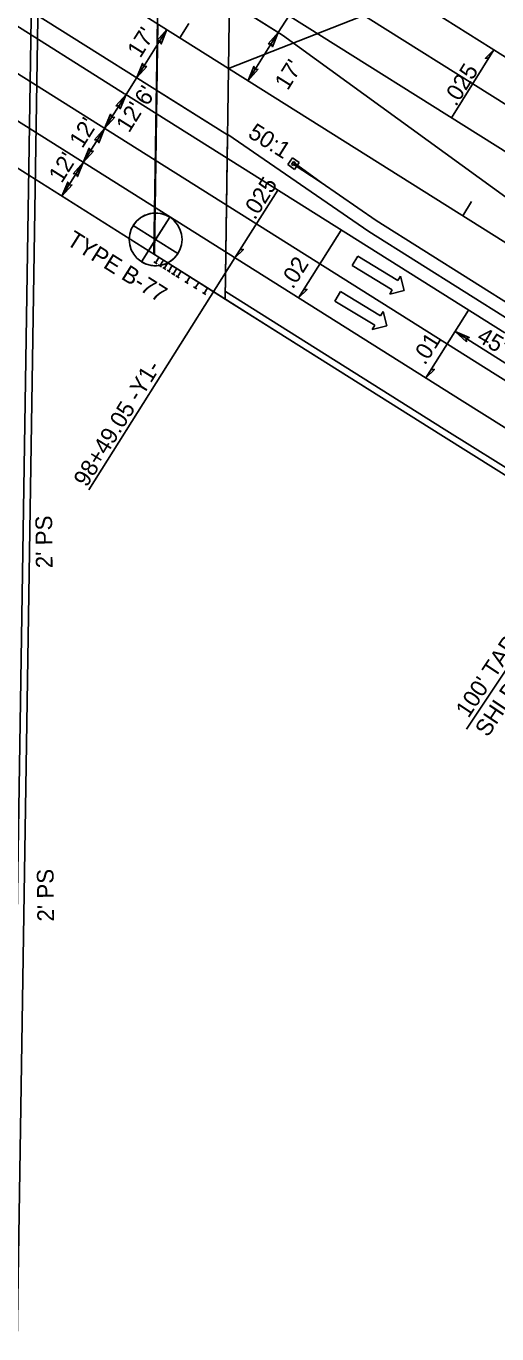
# Model space of a CAD drawing. Extents: x 2389694 to 2405615, y 547005 to 573532.
# Drawn here: x 2397764.3 to 2397905.2, y 552684.1 to 553075.7 of the extents above; entities that cross this region are included whole.
import ezdxf

# ---------------------------------------------------------------- set-up
doc = ezdxf.new("R2010")
doc.units = 0
for name, color, linetype in [('Boring Cell', 7, 'Continuous'), ('Default', 7, 'Continuous'), ('Old_Level_22', 7, 'Continuous'), ('Prop Approach Slab', 7, 'Continuous'), ('Prop Approach Slab Hatching', 7, 'Continuous'), ('Prop Cable Guiderail Anchor Unit CELL', 7, 'Continuous'), ('Prop Cable Guiderail Double Face', 7, 'Continuous'), ('Prop Conc Expressway Gutter', 7, 'Continuous'), ('Prop Dimension', 7, 'Continuous'), ('Prop Dimension Text', 7, 'Continuous'), ('Prop EOT', 7, 'Continuous'), ('Prop Guardrail', 7, 'Continuous'), ('Prop Horizontal Alignment', 7, 'Continuous'), ('Prop Horizontal Alignment Tick Small', 7, 'Continuous'), ('Prop Lane Arrow Through CELL', 7, 'Continuous'), ('Prop Lane Lines', 7, 'Continuous'), ('Prop SAU III Approach CELL', 7, 'Continuous'), ('Prop Super Arrow 1 Lane CELL', 7, 'Continuous'), ('Prop Superelevation Label', 7, 'Continuous')]:
    doc.layers.add(name, color=color, linetype=linetype)

# ---------------------------------------------------------------- blocks, each defined once
blk = doc.blocks.new('B02')
at = {"layer": 'Boring Cell'}
for p, q in [((0, -15.81), (0, 15.81)), ((0.1785, 15.81), (0, 15.81)), ((15.81, 0), (-15.81, 0)), ((15.81, 0), (15.81, 0.1785))]:
    blk.add_line(p, q, dxfattribs=at)
for points in [[(0, 15.81), (0, 0), (-15.81, 0)], [(0, -15.81), (0, 0), (15.81, 0)]]:
    blk.add_lwpolyline(points, dxfattribs=at)
blk.add_circle((0, 0), 15.81, dxfattribs=at)
for start, end in [(89.3557361, 180), (270, 0.6442639)]:
    blk.add_arc((0, 0), 15.81, start, end, dxfattribs=at)

msp = doc.modelspace()

# ---------------------------------------------------------------- linework, layer by layer
at = {"layer": 'Default'}
msp.add_line((2397804.86, 553153.2), (2397802.52, 553007.47), dxfattribs=at)
at = {"layer": 'Prop Approach Slab'}
for p, q in [((2397670.86, 553139.97), (2397824.62, 553043.14)), ((2397670.16, 553090.81), (2397823.92, 552993.99)), ((2397803.47, 553056.47), (2397802.76, 553007.31))]:
    msp.add_line(p, q, dxfattribs=at)
at = {"layer": 'Prop Approach Slab Hatching'}
msp.add_lwpolyline([(2397803.47, 553056.47), (2397824.62, 553043.14), (2397823.92, 552993.99), (2397802.76, 553007.31)], close=True, dxfattribs=at)
at = {"layer": 'Prop Cable Guiderail Anchor Unit CELL'}
for p, q in [((2397842.59, 553034.24), (2397844.01, 553036.3)), ((2397843.77, 553034.31), (2397844.36, 553035.17)), ((2397844.01, 553036.3), (2397846.06, 553034.88)), ((2397844.29, 553033.96), (2397844.88, 553034.81)), ((2397844.36, 553035.17), (2397844.88, 553034.81)), ((2397852.56, 553028.89), (2397844.49, 553034.76)), ((2397844.65, 553032.82), (2397846.06, 553034.88)), ((2397842.59, 553034.24), (2397844.65, 553032.82)), ((2397843.77, 553034.31), (2397844.29, 553033.96)), ((2397852.56, 553028.89), (2397844.19, 553034.37)), ((2397852.56, 553028.89), (2397844.33, 553034.56)), ((2397869.03, 553017.54), (2397852.56, 553028.89)), ((2397852.56, 553028.89), (2397852.56, 553028.89))]:
    msp.add_line(p, q, dxfattribs=at)
at = {"layer": 'Prop Cable Guiderail Double Face'}
msp.add_line((2397869.03, 553017.54), (2397911.83, 552990.59), dxfattribs=at)
at = {"layer": 'Prop Conc Expressway Gutter'}
for p, q in [((2397824.01, 552996.26), (2397889.45, 552955.05)), ((2397889.45, 552955.05), (2397919.6, 552936.07))]:
    msp.add_line(p, q, dxfattribs=at)
at = {"layer": 'Prop Dimension'}
for p, q in [((2397825.91, 553132.18), (2397824.91, 553063.05)), ((2397824.91, 553063.05), (2397970.44, 553120.26)), ((2397839.78, 553073.78), (2397842.98, 553078.86)), ((2397797.41, 553060.28), (2397806.47, 553074.66)), ((2397802.76, 553007.31), (2397803.75, 553076.38)), ((2397830.72, 553059.39), (2397839.78, 553073.78)), ((2397823.92, 552993.99), (2397824.91, 553063.05)), ((2397794.22, 553055.2), (2397797.41, 553060.28)), ((2397787.82, 553045.05), (2397794.22, 553055.2)), ((2397781.43, 553034.89), (2397787.82, 553045.05)), ((2397775.05, 553024.76), (2397781.43, 553034.89)), ((2397826.81, 553006.32), (2397783.04, 552936.81)), ((2397930.74, 552960.25), (2397892.66, 552984.22)), ((2397924.03, 552907.26), (2397896.07, 552865.17))]:
    msp.add_line(p, q, dxfattribs=at)
for points in [[(2397803.42, 553071.27), (2397806.47, 553074.66), (2397804.74, 553070.41), (2397804.37, 553071.32)], [(2397836.73, 553070.38), (2397839.78, 553073.78), (2397838.05, 553069.52), (2397837.68, 553070.44)], [(2397800.47, 553063.67), (2397797.41, 553060.28), (2397799.15, 553064.53), (2397799.52, 553063.62)], [(2397833.78, 553062.79), (2397830.72, 553059.39), (2397832.46, 553063.65), (2397832.83, 553062.74)], [(2397791.16, 553051.81), (2397794.22, 553055.2), (2397792.48, 553050.95), (2397792.11, 553051.86)], [(2397790.88, 553048.44), (2397787.82, 553045.05), (2397789.56, 553049.3), (2397789.93, 553048.39)], [(2397784.77, 553041.65), (2397787.82, 553045.05), (2397786.09, 553040.79), (2397785.72, 553041.7)], [(2397784.48, 553038.29), (2397781.43, 553034.89), (2397783.16, 553039.15), (2397783.53, 553038.23)], [(2397778.37, 553031.5), (2397781.43, 553034.89), (2397779.69, 553030.64), (2397779.32, 553031.55)], [(2397778.1, 553028.16), (2397775.05, 553024.76), (2397776.78, 553029.02), (2397777.15, 553028.1)], [(2397896.06, 552981.17), (2397892.66, 552984.22), (2397896.92, 552982.49), (2397896, 552982.12)]]:
    msp.add_lwpolyline(points, close=True, dxfattribs=at)
at = {"layer": 'Prop EOT'}
for p, q in [((2397759.5, 552671.75), (2397782.16, 554116.88)), ((2397761.5, 552671.72), (2397784.16, 554116.85)), ((2396983.48, 553620.08), (2397932.08, 553022.75)), ((2396958.97, 553581.15), (2397793.8, 553055.47)), ((2397200.04, 553400.99), (2397894.78, 552963.52)), ((2397640.1, 553234.97), (2397944.87, 553043.06)), ((2397825.2, 553082.96), (2397841.06, 553072.97)), ((2397841.06, 553072.97), (2397967.73, 552980.9)), ((2397793.84, 553055.44), (2397907.57, 552983.82)), ((2397824.63, 553043.21), (2397866.9, 553014.16)), ((2397866.9, 553014.16), (2397909.7, 552987.21)), ((2397823.92, 552993.96), (2397888.38, 552953.36)), ((2397894.78, 552963.51), (2397922, 552946.37)), ((2397888.39, 552953.36), (2397915.61, 552936.22))]:
    msp.add_line(p, q, dxfattribs=at)
at = {"layer": 'Prop Guardrail'}
for p, q in [((2397819.91, 553086.29), (2397841.06, 553072.97)), ((2397841.06, 553072.97), (2397967.73, 552980.9)), ((2397818.63, 552997.32), (2397839.76, 552983.98)), ((2397839.76, 552983.98), (2397888.39, 552953.36)), ((2397888.39, 552953.36), (2397915.61, 552936.22))]:
    msp.add_line(p, q, dxfattribs=at)
at = {"layer": 'Prop Horizontal Alignment'}
msp.add_line((2396971.22, 553600.62), (2397933.44, 552994.72), dxfattribs=at)
at = {"layer": 'Prop Horizontal Alignment Tick Small'}
for p, q in [((2397810.35, 553072.23), (2397813.01, 553076.46)), ((2397894.97, 553018.94), (2397897.63, 553023.17))]:
    msp.add_line(p, q, dxfattribs=at)
at = {"layer": 'Prop Lane Arrow Through CELL'}
for p, q in [((2397861.91, 553003.99), (2397863.61, 553006.81)), ((2397873.89, 552996.74), (2397861.91, 553003.99)), ((2397863.61, 553006.81), (2397875.59, 552999.56)), ((2397875.59, 552999.56), (2397876.37, 553000.85)), ((2397876.37, 553000.85), (2397877.46, 552996.56)), ((2397856.66, 552993.39), (2397858.37, 552996.21)), ((2397858.37, 552996.21), (2397870.35, 552988.97)), ((2397873.11, 552995.46), (2397873.89, 552996.74)), ((2397877.46, 552996.56), (2397873.11, 552995.46)), ((2397868.64, 552986.15), (2397856.66, 552993.39)), ((2397870.35, 552988.97), (2397871.12, 552990.25)), ((2397871.12, 552990.25), (2397872.21, 552985.97)), ((2397867.86, 552984.86), (2397868.64, 552986.15)), ((2397872.21, 552985.97), (2397867.86, 552984.86))]:
    msp.add_line(p, q, dxfattribs=at)
at = {"layer": 'Prop Lane Lines'}
for p, q in [((2396989.87, 553630.23), (2397938.47, 553032.9)), ((2396952.57, 553571), (2397901.17, 552973.67)), ((2397901.18, 552973.67), (2397928.4, 552956.53))]:
    msp.add_line(p, q, dxfattribs=at)
at = {"layer": 'Prop SAU III Approach CELL'}
for p, q in [((2397802.76, 553007.31), (2397818.63, 552997.32)), ((2397802.54, 553005.09), (2397803.51, 553004.48)), ((2397804.09, 553006.48), (2397803.02, 553004.78)), ((2397803.86, 553004.26), (2397804.83, 553003.65)), ((2397805.41, 553005.64), (2397804.34, 553003.95)), ((2397805.18, 553003.42), (2397806.15, 553002.81)), ((2397806.73, 553004.81), (2397805.67, 553003.12)), ((2397808.05, 553003.98), (2397806.99, 553002.29)), ((2397806.5, 553002.59), (2397807.47, 553001.98)), ((2397807.83, 553001.76), (2397808.79, 553001.15)), ((2397809.38, 553003.15), (2397808.31, 553001.45)), ((2397809.15, 553000.93), (2397810.12, 553000.32)), ((2397810.7, 553002.31), (2397809.63, 553000.62)), ((2397813.34, 553000.65), (2397812.28, 552998.96)), ((2397811.79, 552999.26), (2397812.76, 552998.65)), ((2397814.44, 552997.6), (2397815.41, 552996.99)), ((2397815.99, 552998.98), (2397814.92, 552997.29)), ((2397817.08, 552995.93), (2397818.05, 552995.32)), ((2397818.63, 552997.32), (2397817.57, 552995.63))]:
    msp.add_line(p, q, dxfattribs=at)
at = {"layer": 'Prop Super Arrow 1 Lane CELL'}
for p, q in [((2397891.61, 553048.23), (2397904.25, 553068.63)), ((2397839.59, 553026.63), (2397826.81, 553006.32)), ((2397858.63, 553014.64), (2397845.85, 552994.33)), ((2397896.71, 552990.66), (2397883.92, 552970.35))]:
    msp.add_line(p, q, dxfattribs=at)
for points in [[(2397904.25, 553068.63), (2397901.73, 553066.08), (2397902.7, 553066.13)], [(2397826.81, 553006.32), (2397829.35, 553008.85), (2397828.38, 553008.81)], [(2397845.85, 552994.33), (2397848.39, 552996.86), (2397847.42, 552996.83)], [(2397883.92, 552970.35), (2397886.47, 552972.89), (2397885.5, 552972.85)]]:
    msp.add_lwpolyline(points, close=True, dxfattribs=at)

# ---------------------------------------------------------------- block references
at = {"layer": 'Boring Cell', "xscale": 0.5, "yscale": 0.5, "rotation": -32.16749301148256}
msp.add_blockref('B02', (2397803.07, 553011.83), dxfattribs=at)

# ---------------------------------------------------------------- texts
at = {"layer": 'Old_Level_22'}
for s, p in [("100' TAPER &", (2397896.67, 552868.26)), ('SHLDR TRANS', (2397902.46, 552862.52))]:
    msp.add_text(s, height=5, rotation=56.3289, dxfattribs=at).set_placement(p)
at = {"layer": 'Prop Dimension Text'}
for s, rotation, p in [("17'", 57.9134, (2397798.48, 553065.9)), ("17'", 57.9134, (2397842.59, 553056.23)), ("6'", 57.9134, (2397800.66, 553051.55)), ("12'", 57.9134, (2397795.13, 553043.53)), ("12'", 57.9134, (2397781.15, 553038.86)), ('50:1', 327.8032, (2397830.37, 553042.7)), ("12'", 57.9134, (2397774.97, 553028.43)), ('TYPE B-77', 327.8032, (2397776.11, 553010.5)), ("45' TYP.", 329.5519, (2397898.85, 552981.57)), ('98+49.05 -Y1-', 58.3838, (2397782.45, 552937.41)), ("2' PS", 90.5836, (2397772.24, 552913.39)), ("2' PS", 90.5836, (2397772.68, 552807.58))]:
    msp.add_text(s, height=5, rotation=rotation, dxfattribs=at).set_placement(p)
at = {"layer": 'Prop Superelevation Label'}
for s, rotation, p in [('.025', 58.2085, (2397892.95, 553051.41)), ('.025', 57.8016, (2397832.77, 553017.44)), ('.02', 57.8016, (2397844.12, 552996.72)), ('.01', 57.8016, (2397883.65, 552973.94))]:
    msp.add_text(s, height=5, rotation=rotation, dxfattribs=at).set_placement(p)

doc.saveas('drawing.dxf')
